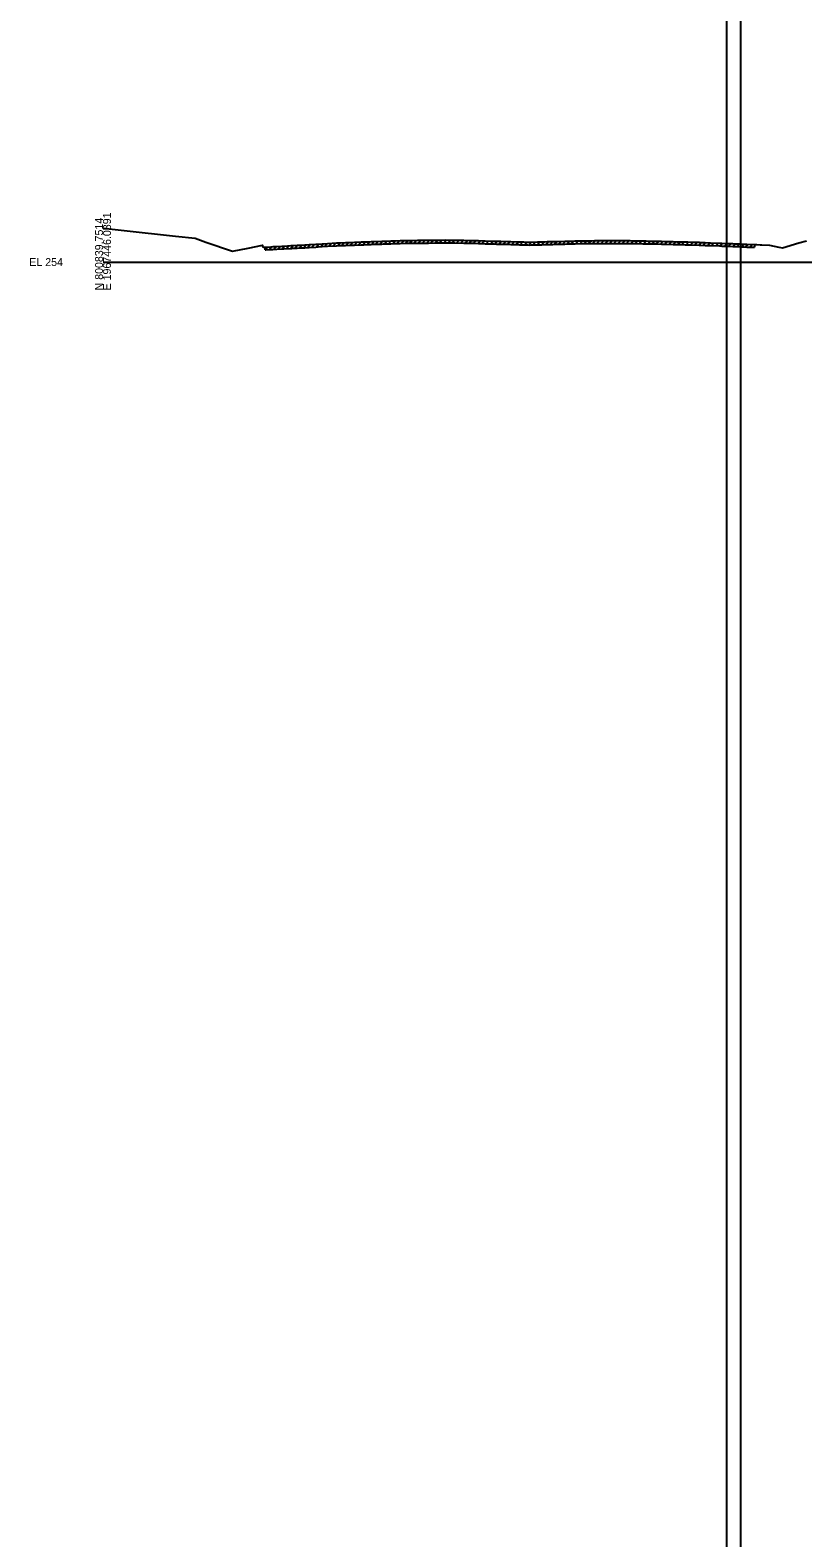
# Model space of a CAD drawing. Extents: x -119 to 6018, y -82 to 34226.
# Drawn here: x -26 to 247, y 23050 to 23582 of the extents above; entities that cross this region are included whole.
import ezdxf

# ---------------------------------------------------------------- set-up
doc = ezdxf.new("R2010")
doc.units = 0
for name, color, linetype in [('Default', 7, 'Continuous'), ('RD_GPK_XS_Cell', 7, 'Continuous'), ('RD_Sketch1', 7, 'Continuous'), ('RD_XS_ExGround', 7, 'Continuous'), ('RD_XS_ExPaveRet', 7, 'Continuous')]:
    doc.layers.add(name, color=color, linetype=linetype)

msp = doc.modelspace()

# ---------------------------------------------------------------- linework, layer by layer
at = {"layer": 'RD_GPK_XS_Cell'}
msp.add_line((0, 23500), (300, 23500), dxfattribs=at)
at = {"layer": 'RD_Sketch1'}
for p, q in [((220, -82), (220, 34226.15)), ((225, -82), (225, 34226.15))]:
    msp.add_line(p, q, dxfattribs=at)
at = {"layer": 'RD_XS_ExGround'}
msp.add_lwpolyline([(0, 23511.86), (1.14, 23511.9), (7.47, 23511.09), (25.56, 23509.1), (32.51, 23508.38), (36.26, 23507.04), (45.62, 23503.88), (51.24, 23504.94), (56.21, 23505.93), (56.31, 23505.48), (56.7, 23505.26), (57.47, 23505.31), (59.17, 23505.41), (59.86, 23505.45), (61.32, 23505.52), (63.12, 23505.62), (63.49, 23505.65), (63.8, 23505.66), (66.25, 23505.8), (66.64, 23505.82), (67.13, 23505.85), (68.45, 23505.93), (69.5, 23505.98), (71.13, 23506.07), (72.71, 23506.17), (75.1, 23506.31), (75.93, 23506.36), (77.34, 23506.44), (79.22, 23506.56), (82.34, 23506.75), (82.91, 23506.79), (83.59, 23506.83), (85.55, 23506.9), (86.99, 23506.95), (88.71, 23507.01), (91, 23507.1), (91.53, 23507.12), (91.96, 23507.13), (93.41, 23507.19), (94.62, 23507.25), (95.01, 23507.27), (95.36, 23507.28), (98.29, 23507.36), (98.95, 23507.38), (101.54, 23507.47), (102.91, 23507.51), (104.83, 23507.58), (106.88, 23507.64), (108.2, 23507.66), (108.92, 23507.66), (110.87, 23507.68), (111.42, 23507.68), (112.81, 23507.7), (114.85, 23507.72), (117.75, 23507.77), (118.28, 23507.78), (118.86, 23507.78), (120.94, 23507.79), (122.83, 23507.75), (124.09, 23507.73), (127.28, 23507.67), (129.1, 23507.64), (130.72, 23507.61), (132.43, 23507.57), (133.88, 23507.52), (134.79, 23507.49), (136.98, 23507.42), (137.8, 23507.39), (138.76, 23507.37), (140.29, 23507.32), (142.69, 23507.27), (143.22, 23507.26), (143.84, 23507.24), (145.89, 23507.17), (146.62, 23507.14), (147.06, 23507.12), (147.6, 23507.11), (148.1, 23507.09), (148.41, 23507.08), (149.78, 23507.04), (150.32, 23507.01), (151.04, 23507.03), (153.26, 23507.09), (153.75, 23507.11), (154.75, 23507.13), (155.83, 23507.17), (156.64, 23507.2), (157.36, 23507.21), (158.61, 23507.24), (159.12, 23507.26), (159.57, 23507.28), (160.26, 23507.29), (162.85, 23507.36), (163.71, 23507.38), (165.93, 23507.43), (166.55, 23507.45), (169.04, 23507.52), (170.52, 23507.54), (171.5, 23507.55), (172.37, 23507.55), (173.37, 23507.56), (174.51, 23507.56), (175.57, 23507.57), (176.81, 23507.57), (178.47, 23507.58), (178.81, 23507.58), (179.98, 23507.58), (181.87, 23507.59), (182.46, 23507.59), (184.06, 23507.59), (185.28, 23507.57), (185.82, 23507.57), (186.46, 23507.55), (188.42, 23507.52), (190.46, 23507.48), (191.05, 23507.47), (191.6, 23507.46), (192.92, 23507.43), (194.42, 23507.4), (195.01, 23507.38), (197.01, 23507.33), (198.07, 23507.31), (198.39, 23507.3), (201.13, 23507.22), (202.34, 23507.19), (203.47, 23507.16), (204.47, 23507.14), (205.34, 23507.12), (206.32, 23507.09), (207.78, 23507.05), (210.3, 23506.97), (210.85, 23506.95), (212.39, 23506.88), (214.32, 23506.8), (217.39, 23506.68), (218.25, 23506.65), (220.43, 23506.57), (220.76, 23506.56), (222.17, 23506.5), (223, 23506.47), (223.69, 23506.44), (224.86, 23506.39), (226.17, 23506.34), (227.06, 23506.31), (229.78, 23506.21), (230.67, 23506.17), (231.81, 23506.12), (232.39, 23506.1), (235.09, 23506), (238.32, 23505.2), (239.67, 23504.97), (245.47, 23506.81), (248.14, 23507.5)], dxfattribs=at)
at = {"layer": 'RD_XS_ExPaveRet'}
for p, q in [((66.16, 23504.79), (67.22, 23505.86)), ((67.66, 23504.88), (68.72, 23505.94)), ((69.16, 23504.96), (70.21, 23506.02)), ((70.66, 23505.05), (71.72, 23506.11)), ((72.16, 23505.13), (73.22, 23506.2)), ((73.66, 23505.22), (74.72, 23506.28)), ((75.16, 23505.31), (76.22, 23506.37)), ((76.66, 23505.4), (77.72, 23506.47)), ((78.16, 23505.5), (79.22, 23506.56)), ((79.66, 23505.59), (80.72, 23506.65)), ((81.16, 23505.68), (82.22, 23506.75)), ((82.66, 23505.77), (83.72, 23506.83)), ((82.91, 23505.79), (83.59, 23505.83)), ((83.59, 23505.83), (85.55, 23505.9)), ((84.16, 23505.85), (85.19, 23506.88)), ((85.55, 23505.9), (86.99, 23505.95)), ((85.66, 23505.9), (86.69, 23506.94)), ((86.99, 23505.95), (88.71, 23506.01)), ((87.16, 23505.95), (88.2, 23506.99)), ((88.66, 23506.01), (89.7, 23507.05)), ((88.71, 23506.01), (91, 23506.1)), ((90.16, 23506.06), (91.2, 23507.1)), ((91, 23506.1), (91.53, 23506.12)), ((91.53, 23506.12), (91.96, 23506.13)), ((91.66, 23506.12), (92.7, 23507.16)), ((91.96, 23506.13), (93.41, 23506.19)), ((93.16, 23506.18), (94.21, 23507.23)), ((93.41, 23506.19), (94.62, 23506.25)), ((94.62, 23506.25), (95.01, 23506.27)), ((94.66, 23506.25), (95.7, 23507.29)), ((95.01, 23506.27), (95.36, 23506.28)), ((95.36, 23506.28), (98.29, 23506.36)), ((96.16, 23506.3), (97.19, 23507.33)), ((97.66, 23506.35), (98.69, 23507.38)), ((98.29, 23506.36), (98.95, 23506.38)), ((98.95, 23506.38), (101.54, 23506.47)), ((99.16, 23506.39), (100.19, 23507.43)), ((100.66, 23506.44), (101.69, 23507.48)), ((101.54, 23506.47), (102.91, 23506.51)), ((102.16, 23506.49), (103.19, 23507.52)), ((102.91, 23506.51), (104.83, 23506.58)), ((103.66, 23506.54), (104.69, 23507.58)), ((104.83, 23506.58), (106.88, 23506.64)), ((105.16, 23506.59), (106.19, 23507.62)), ((106.66, 23506.63), (107.67, 23507.65)), ((106.88, 23506.64), (108.2, 23506.66)), ((108.16, 23506.66), (109.16, 23507.66)), ((108.2, 23506.66), (108.92, 23506.66)), ((108.92, 23506.66), (110.87, 23506.68)), ((109.66, 23506.67), (110.66, 23507.67)), ((110.87, 23506.68), (111.42, 23506.68)), ((111.16, 23506.68), (112.17, 23507.69)), ((111.42, 23506.68), (112.81, 23506.7)), ((112.66, 23506.69), (113.67, 23507.71)), ((112.81, 23506.7), (114.85, 23506.72)), ((114.16, 23506.71), (115.17, 23507.73)), ((114.85, 23506.72), (117.75, 23506.77)), ((115.66, 23506.73), (116.67, 23507.75)), ((117.16, 23506.76), (118.17, 23507.77)), ((117.75, 23506.77), (118.28, 23506.78)), ((118.28, 23506.78), (118.86, 23506.78)), ((118.66, 23506.78), (119.66, 23507.78)), ((118.86, 23506.78), (120.94, 23506.79)), ((120.16, 23506.79), (121.15, 23507.78)), ((120.94, 23506.79), (122.83, 23506.75)), ((121.66, 23506.77), (122.64, 23507.76)), ((122.83, 23506.75), (124.09, 23506.73)), ((123.16, 23506.75), (124.14, 23507.73)), ((124.09, 23506.73), (127.28, 23506.67)), ((124.66, 23506.72), (125.64, 23507.7)), ((126.16, 23506.69), (127.14, 23507.68)), ((127.28, 23506.67), (129.1, 23506.64)), ((127.66, 23506.67), (128.64, 23507.65)), ((129.1, 23506.64), (130.72, 23506.61)), ((129.16, 23506.64), (130.14, 23507.62)), ((130.66, 23506.61), (131.63, 23507.59)), ((130.72, 23506.61), (132.43, 23506.57)), ((132.16, 23506.57), (133.13, 23507.54)), ((132.43, 23506.57), (133.88, 23506.52)), ((133.66, 23506.53), (134.62, 23507.49)), ((133.88, 23506.52), (134.79, 23506.49)), ((134.79, 23506.49), (136.98, 23506.42)), ((135.16, 23506.48), (136.13, 23507.45)), ((136.66, 23506.43), (137.63, 23507.4)), ((136.98, 23506.42), (137.8, 23506.39)), ((137.8, 23506.39), (138.76, 23506.37)), ((138.16, 23506.38), (139.13, 23507.36)), ((138.76, 23506.37), (140.29, 23506.32)), ((139.66, 23506.34), (140.63, 23507.32)), ((140.29, 23506.32), (142.69, 23506.27)), ((141.16, 23506.3), (142.13, 23507.28)), ((142.66, 23506.27), (143.64, 23507.25)), ((142.69, 23506.27), (143.22, 23506.26)), ((143.22, 23506.26), (143.84, 23506.24)), ((143.84, 23506.24), (145.89, 23506.17)), ((144.16, 23506.23), (145.12, 23507.2)), ((145.66, 23506.18), (146.62, 23507.14)), ((145.89, 23506.17), (146.62, 23506.14)), ((146.62, 23506.14), (147.06, 23506.12)), ((147.06, 23506.12), (147.6, 23506.11)), ((147.16, 23506.12), (148.13, 23507.09)), ((147.6, 23506.11), (148.1, 23506.09)), ((148.1, 23506.09), (148.41, 23506.08)), ((148.41, 23506.08), (149.78, 23506.04)), ((148.66, 23506.07), (149.63, 23507.05)), ((149.78, 23506.04), (150.32, 23506.01)), ((150.16, 23506.02), (151.17, 23507.03)), ((150.32, 23506.01), (151.04, 23506.03)), ((151.04, 23506.03), (153.26, 23506.09)), ((151.66, 23506.05), (152.69, 23507.08)), ((153.16, 23506.09), (154.18, 23507.12)), ((153.26, 23506.09), (153.75, 23506.11)), ((153.75, 23506.11), (154.75, 23506.13)), ((154.66, 23506.13), (155.69, 23507.16)), ((154.75, 23506.13), (155.83, 23506.17)), ((155.83, 23506.17), (156.64, 23506.2)), ((156.16, 23506.18), (157.19, 23507.21)), ((156.64, 23506.2), (157.36, 23506.21)), ((157.36, 23506.21), (158.61, 23506.24)), ((157.66, 23506.22), (158.68, 23507.25)), ((158.61, 23506.24), (159.12, 23506.26)), ((159.12, 23506.26), (159.57, 23506.28)), ((159.16, 23506.26), (160.19, 23507.29)), ((159.57, 23506.28), (160.26, 23506.29)), ((160.26, 23506.29), (162.85, 23506.36)), ((160.66, 23506.3), (161.68, 23507.33)), ((162.16, 23506.34), (163.18, 23507.36)), ((162.85, 23506.36), (163.71, 23506.38)), ((163.66, 23506.38), (164.68, 23507.4)), ((163.71, 23506.38), (165.93, 23506.43)), ((165.16, 23506.41), (166.18, 23507.44)), ((165.93, 23506.43), (166.55, 23506.45)), ((166.55, 23506.45), (169.04, 23506.52)), ((166.66, 23506.45), (167.68, 23507.48)), ((168.16, 23506.49), (169.18, 23507.52)), ((169.04, 23506.52), (170.52, 23506.54)), ((169.66, 23506.53), (170.67, 23507.54)), ((170.52, 23506.54), (171.5, 23506.55)), ((171.16, 23506.55), (172.16, 23507.55)), ((171.5, 23506.55), (172.37, 23506.55)), ((172.37, 23506.55), (173.37, 23506.56)), ((172.66, 23506.55), (173.66, 23507.56)), ((173.37, 23506.56), (174.51, 23506.56)), ((174.16, 23506.56), (175.16, 23507.56)), ((174.51, 23506.56), (175.57, 23506.57)), ((175.57, 23506.57), (176.81, 23506.57)), ((175.66, 23506.57), (176.66, 23507.57)), ((176.81, 23506.57), (178.47, 23506.58)), ((177.16, 23506.57), (178.16, 23507.58)), ((178.47, 23506.58), (178.81, 23506.58)), ((178.66, 23506.58), (179.66, 23507.58)), ((178.81, 23506.58), (179.98, 23506.58)), ((179.98, 23506.58), (181.87, 23506.59)), ((180.16, 23506.58), (181.16, 23507.59)), ((181.66, 23506.59), (182.66, 23507.59)), ((181.87, 23506.59), (182.46, 23506.59)), ((182.46, 23506.59), (184.06, 23506.59)), ((183.16, 23506.59), (184.16, 23507.59)), ((184.06, 23506.59), (185.28, 23506.57)), ((184.66, 23506.58), (185.64, 23507.57)), ((185.28, 23506.57), (185.82, 23506.57)), ((185.82, 23506.57), (186.46, 23506.55)), ((186.16, 23506.56), (187.14, 23507.54)), ((186.46, 23506.55), (188.42, 23506.52)), ((187.66, 23506.53), (188.64, 23507.51)), ((188.42, 23506.52), (190.46, 23506.48)), ((189.16, 23506.5), (190.14, 23507.49)), ((190.46, 23506.48), (191.05, 23506.47)), ((190.66, 23506.48), (191.64, 23507.46)), ((191.05, 23506.47), (191.6, 23506.46)), ((191.6, 23506.46), (192.92, 23506.43)), ((192.16, 23506.44), (193.14, 23507.42)), ((192.92, 23506.43), (194.42, 23506.4)), ((193.66, 23506.41), (194.64, 23507.39)), ((194.42, 23506.4), (195.01, 23506.38)), ((195.01, 23506.38), (197.01, 23506.33)), ((195.16, 23506.38), (196.13, 23507.35)), ((196.66, 23506.34), (197.63, 23507.32)), ((197.01, 23506.33), (198.07, 23506.31)), ((198.07, 23506.31), (198.39, 23506.3)), ((198.16, 23506.3), (199.13, 23507.28)), ((198.39, 23506.3), (201.13, 23506.22)), ((199.66, 23506.26), (200.63, 23507.24)), ((201.13, 23506.22), (202.34, 23506.19)), ((201.16, 23506.22), (202.13, 23507.2)), ((202.34, 23506.19), (203.47, 23506.16)), ((202.66, 23506.18), (203.63, 23507.16)), ((203.47, 23506.16), (204.47, 23506.14)), ((204.16, 23506.15), (205.13, 23507.12)), ((204.47, 23506.14), (205.34, 23506.12)), ((205.34, 23506.12), (206.32, 23506.09)), ((205.66, 23506.11), (206.63, 23507.08)), ((206.32, 23506.09), (207.78, 23506.05)), ((207.16, 23506.07), (208.13, 23507.04)), ((207.78, 23506.05), (210.3, 23505.97)), ((208.66, 23506.02), (209.63, 23506.99)), ((210.16, 23505.98), (211.12, 23506.94)), ((210.3, 23505.97), (210.85, 23505.95)), ((210.85, 23505.95), (212.39, 23505.88)), ((211.66, 23505.92), (212.62, 23506.87)), ((212.39, 23505.88), (214.32, 23505.8)), ((213.16, 23505.85), (214.11, 23506.81)), ((214.66, 23505.79), (215.62, 23506.75)), ((216.16, 23505.73), (217.12, 23506.69)), ((217.66, 23505.67), (218.62, 23506.64)), ((219.16, 23505.62), (220.12, 23506.59)), ((220.66, 23505.56), (221.61, 23506.52)), ((222.16, 23505.5), (223.12, 23506.46)), ((223.66, 23505.44), (224.62, 23506.4)), ((225.16, 23505.38), (226.12, 23506.34)), ((226.66, 23505.33), (227.62, 23506.29)), ((228.16, 23505.27), (229.12, 23506.23)), ((229.78, 23506.21), (229.78, 23505.21)), ((57.16, 23504.29), (58.22, 23505.35)), ((57.16, 23504.29), (57.16, 23505.29)), ((57.16, 23504.29), (57.47, 23504.31)), ((57.47, 23504.31), (59.17, 23504.41)), ((58.66, 23504.38), (59.72, 23505.44)), ((59.17, 23504.41), (59.86, 23504.45)), ((59.86, 23504.45), (61.32, 23504.52)), ((60.16, 23504.46), (61.21, 23505.52)), ((61.32, 23504.52), (63.12, 23504.62)), ((61.66, 23504.54), (62.72, 23505.6)), ((63.12, 23504.62), (63.49, 23504.65)), ((63.16, 23504.63), (64.22, 23505.69)), ((63.49, 23504.65), (63.8, 23504.66)), ((63.8, 23504.66), (66.25, 23504.8)), ((64.66, 23504.71), (65.72, 23505.77)), ((66.25, 23504.8), (66.64, 23504.82)), ((66.64, 23504.82), (67.13, 23504.85)), ((67.13, 23504.85), (68.45, 23504.93)), ((68.45, 23504.93), (69.5, 23504.98)), ((69.5, 23504.98), (71.13, 23505.07)), ((71.13, 23505.07), (72.71, 23505.17)), ((72.71, 23505.17), (75.1, 23505.31)), ((75.1, 23505.31), (75.93, 23505.36)), ((75.93, 23505.36), (77.34, 23505.44)), ((77.34, 23505.44), (79.22, 23505.56)), ((79.22, 23505.56), (82.34, 23505.75)), ((82.34, 23505.75), (82.91, 23505.79)), ((214.32, 23505.8), (217.39, 23505.68)), ((217.39, 23505.68), (218.25, 23505.65)), ((218.25, 23505.65), (220.43, 23505.57)), ((220.43, 23505.57), (220.76, 23505.56)), ((220.76, 23505.56), (222.17, 23505.5)), ((222.17, 23505.5), (223, 23505.47)), ((223, 23505.47), (223.69, 23505.44)), ((223.69, 23505.44), (224.86, 23505.39)), ((224.86, 23505.39), (226.17, 23505.34)), ((226.17, 23505.34), (227.06, 23505.31)), ((227.06, 23505.31), (229.78, 23505.21))]:
    msp.add_line(p, q, dxfattribs=at)

# ---------------------------------------------------------------- texts
at = {"layer": 'Default'}
msp.add_text('-', height=0.0001, dxfattribs=at).set_placement((0, 23500))
at = {"layer": 'RD_GPK_XS_Cell'}
for s, p in [('E 1967446.0891', (2.8, 23490)), ('N 800839.7514', (0, 23490))]:
    msp.add_text(s, height=2.8, rotation=90, dxfattribs=at).set_placement(p)
msp.add_text('EL 254', height=2.8, dxfattribs=at).set_placement((-26, 23498.6))

doc.saveas('drawing.dxf')
